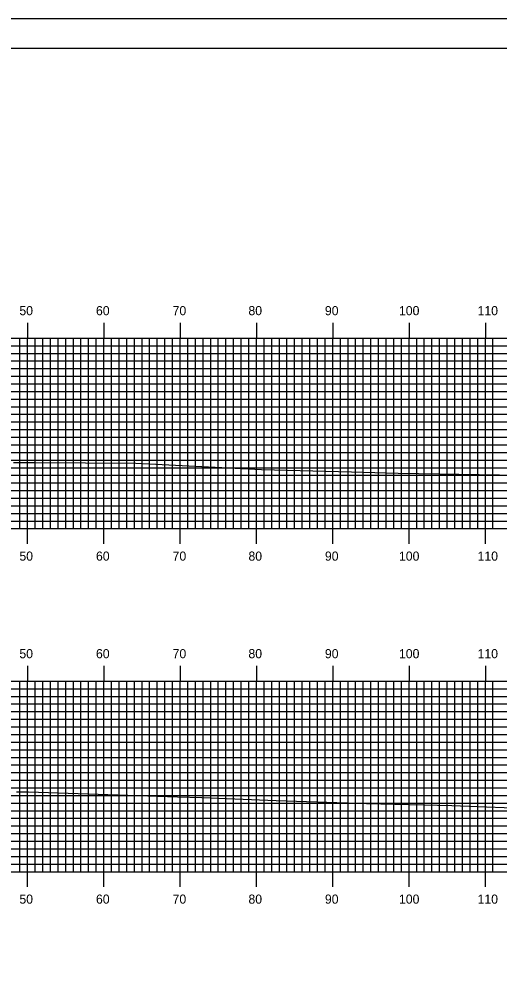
# Model space of a CAD drawing. Extents: x 1780680 to 1781023, y 442591 to 442811.
# Drawn here: x 1780894.2 to 1780957.2, y 442686.7 to 442810.5 of the extents above; entities that cross this region are included whole.
import ezdxf

# ---------------------------------------------------------------- set-up
doc = ezdxf.new("R2010")
doc.units = 0
for name, color, linetype in [('BORDER', 7, 'Continuous'), ('H_V ANNOTATION', 7, 'Continuous'), ('MAJOR', 7, 'Continuous'), ('MINOR', 7, 'Continuous'), ('PLOT BOUNDARY', 7, 'Continuous'), ('S_Roadway_Centerline', 7, 'Continuous')]:
    doc.layers.add(name, color=color, linetype=linetype)

msp = doc.modelspace()

# ---------------------------------------------------------------- linework, layer by layer
at = {"layer": 'BORDER'}
msp.add_lwpolyline([(1780695.78, 442596.67), (1781015.78, 442596.67), (1781015.78, 442806.67), (1780695.78, 442806.67)], close=True, dxfattribs=at)
at = {"layer": 'MAJOR'}
for p, q in [((1780895.38, 442770.67), (1780895.38, 442768.67)), ((1780905.38, 442770.67), (1780905.38, 442768.67)), ((1780915.38, 442770.67), (1780915.38, 442768.67)), ((1780925.38, 442770.67), (1780925.38, 442768.67)), ((1780935.38, 442770.67), (1780935.38, 442768.67)), ((1780945.38, 442770.67), (1780945.38, 442768.67)), ((1780955.38, 442770.67), (1780955.38, 442768.67)), ((1780705.38, 442768.67), (1780985.38, 442768.67)), ((1780705.38, 442768.67), (1780985.38, 442768.67)), ((1780895.38, 442743.67), (1780895.38, 442768.67)), ((1780905.38, 442743.67), (1780905.38, 442768.67)), ((1780915.38, 442743.67), (1780915.38, 442768.67)), ((1780925.38, 442743.67), (1780925.38, 442768.67)), ((1780935.38, 442743.67), (1780935.38, 442768.67)), ((1780945.38, 442743.67), (1780945.38, 442768.67)), ((1780955.38, 442743.67), (1780955.38, 442768.67)), ((1780705.38, 442763.67), (1780985.38, 442763.67)), ((1780705.38, 442758.67), (1780985.38, 442758.67)), ((1780705.38, 442753.67), (1780985.38, 442753.67)), ((1780705.38, 442748.67), (1780985.38, 442748.67)), ((1780705.38, 442743.67), (1780985.38, 442743.67)), ((1780705.38, 442743.67), (1780985.38, 442743.67)), ((1780895.38, 442741.66), (1780895.38, 442743.67)), ((1780905.38, 442741.66), (1780905.38, 442743.67)), ((1780915.38, 442741.66), (1780915.38, 442743.67)), ((1780925.38, 442741.66), (1780925.38, 442743.67)), ((1780935.38, 442741.66), (1780935.38, 442743.67)), ((1780945.38, 442741.66), (1780945.38, 442743.67)), ((1780955.38, 442741.66), (1780955.38, 442743.67)), ((1780895.38, 442725.67), (1780895.38, 442723.67)), ((1780905.38, 442725.67), (1780905.38, 442723.67)), ((1780915.38, 442725.67), (1780915.38, 442723.67)), ((1780925.38, 442725.67), (1780925.38, 442723.67)), ((1780935.38, 442725.67), (1780935.38, 442723.67)), ((1780945.38, 442725.67), (1780945.38, 442723.67)), ((1780955.38, 442725.67), (1780955.38, 442723.67)), ((1780705.38, 442723.67), (1780985.38, 442723.67)), ((1780705.38, 442723.67), (1780985.38, 442723.67)), ((1780895.38, 442698.67), (1780895.38, 442723.67)), ((1780905.38, 442698.67), (1780905.38, 442723.67)), ((1780915.38, 442698.67), (1780915.38, 442723.67)), ((1780925.38, 442698.67), (1780925.38, 442723.67)), ((1780935.38, 442698.67), (1780935.38, 442723.67)), ((1780945.38, 442698.67), (1780945.38, 442723.67)), ((1780955.38, 442698.67), (1780955.38, 442723.67)), ((1780705.38, 442718.67), (1780985.38, 442718.67)), ((1780705.38, 442713.67), (1780985.38, 442713.67)), ((1780705.38, 442708.67), (1780985.38, 442708.67)), ((1780705.38, 442703.67), (1780985.38, 442703.67)), ((1780705.38, 442698.67), (1780985.38, 442698.67)), ((1780705.38, 442698.67), (1780985.38, 442698.67)), ((1780895.38, 442696.66), (1780895.38, 442698.67)), ((1780905.38, 442696.66), (1780905.38, 442698.67)), ((1780915.38, 442696.66), (1780915.38, 442698.67)), ((1780925.38, 442696.66), (1780925.38, 442698.67)), ((1780935.38, 442696.66), (1780935.38, 442698.67)), ((1780945.38, 442696.66), (1780945.38, 442698.67)), ((1780955.38, 442696.66), (1780955.38, 442698.67))]:
    msp.add_line(p, q, dxfattribs=at)
at = {"layer": 'MINOR'}
for p, q in [((1780894.38, 442743.67), (1780894.38, 442768.67)), ((1780896.38, 442743.67), (1780896.38, 442768.67)), ((1780897.38, 442743.67), (1780897.38, 442768.67)), ((1780898.38, 442743.67), (1780898.38, 442768.67)), ((1780899.38, 442743.67), (1780899.38, 442768.67)), ((1780900.38, 442743.67), (1780900.38, 442768.67)), ((1780901.38, 442743.67), (1780901.38, 442768.67)), ((1780902.38, 442743.67), (1780902.38, 442768.67)), ((1780903.38, 442743.67), (1780903.38, 442768.67)), ((1780904.38, 442743.67), (1780904.38, 442768.67)), ((1780906.38, 442743.67), (1780906.38, 442768.67)), ((1780907.38, 442743.67), (1780907.38, 442768.67)), ((1780908.38, 442743.67), (1780908.38, 442768.67)), ((1780909.38, 442743.67), (1780909.38, 442768.67)), ((1780910.38, 442743.67), (1780910.38, 442768.67)), ((1780911.38, 442743.67), (1780911.38, 442768.67)), ((1780912.38, 442743.67), (1780912.38, 442768.67)), ((1780913.38, 442743.67), (1780913.38, 442768.67)), ((1780914.38, 442743.67), (1780914.38, 442768.67)), ((1780916.38, 442743.67), (1780916.38, 442768.67)), ((1780917.38, 442743.67), (1780917.38, 442768.67)), ((1780918.38, 442743.67), (1780918.38, 442768.67)), ((1780919.38, 442743.67), (1780919.38, 442768.67)), ((1780920.38, 442743.67), (1780920.38, 442768.67)), ((1780921.38, 442743.67), (1780921.38, 442768.67)), ((1780922.38, 442743.67), (1780922.38, 442768.67)), ((1780923.38, 442743.67), (1780923.38, 442768.67)), ((1780924.38, 442743.67), (1780924.38, 442768.67)), ((1780926.38, 442743.67), (1780926.38, 442768.67)), ((1780927.38, 442743.67), (1780927.38, 442768.67)), ((1780928.38, 442743.67), (1780928.38, 442768.67)), ((1780929.38, 442743.67), (1780929.38, 442768.67)), ((1780930.38, 442743.67), (1780930.38, 442768.67)), ((1780931.38, 442743.67), (1780931.38, 442768.67)), ((1780932.38, 442743.67), (1780932.38, 442768.67)), ((1780933.38, 442743.67), (1780933.38, 442768.67)), ((1780934.38, 442743.67), (1780934.38, 442768.67)), ((1780936.38, 442743.67), (1780936.38, 442768.67)), ((1780937.38, 442743.67), (1780937.38, 442768.67)), ((1780938.38, 442743.67), (1780938.38, 442768.67)), ((1780939.38, 442743.67), (1780939.38, 442768.67)), ((1780940.38, 442743.67), (1780940.38, 442768.67)), ((1780941.38, 442743.67), (1780941.38, 442768.67)), ((1780942.38, 442743.67), (1780942.38, 442768.67)), ((1780943.38, 442743.67), (1780943.38, 442768.67)), ((1780944.38, 442743.67), (1780944.38, 442768.67)), ((1780946.38, 442743.67), (1780946.38, 442768.67)), ((1780947.38, 442743.67), (1780947.38, 442768.67)), ((1780948.38, 442743.67), (1780948.38, 442768.67)), ((1780949.38, 442743.67), (1780949.38, 442768.67)), ((1780950.38, 442743.67), (1780950.38, 442768.67)), ((1780951.38, 442743.67), (1780951.38, 442768.67)), ((1780952.38, 442743.67), (1780952.38, 442768.67)), ((1780953.38, 442743.67), (1780953.38, 442768.67)), ((1780954.38, 442743.67), (1780954.38, 442768.67)), ((1780956.38, 442743.67), (1780956.38, 442768.67)), ((1780705.38, 442767.67), (1780985.38, 442767.67)), ((1780705.38, 442766.67), (1780985.38, 442766.67)), ((1780705.38, 442765.67), (1780985.38, 442765.67)), ((1780705.38, 442764.67), (1780985.38, 442764.67)), ((1780705.38, 442762.67), (1780985.38, 442762.67)), ((1780705.38, 442761.67), (1780985.38, 442761.67)), ((1780705.38, 442760.67), (1780985.38, 442760.67)), ((1780705.38, 442759.67), (1780985.38, 442759.67)), ((1780705.38, 442757.67), (1780985.38, 442757.67)), ((1780705.38, 442756.67), (1780985.38, 442756.67)), ((1780705.38, 442755.67), (1780985.38, 442755.67)), ((1780705.38, 442754.67), (1780985.38, 442754.67)), ((1780705.38, 442752.67), (1780985.38, 442752.67)), ((1780705.38, 442751.67), (1780985.38, 442751.67)), ((1780705.38, 442750.67), (1780985.38, 442750.67)), ((1780705.38, 442749.67), (1780985.38, 442749.67)), ((1780705.38, 442747.67), (1780985.38, 442747.67)), ((1780705.38, 442746.67), (1780985.38, 442746.67)), ((1780705.38, 442745.67), (1780985.38, 442745.67)), ((1780705.38, 442744.67), (1780985.38, 442744.67)), ((1780894.38, 442698.67), (1780894.38, 442723.67)), ((1780896.38, 442698.67), (1780896.38, 442723.67)), ((1780897.38, 442698.67), (1780897.38, 442723.67)), ((1780898.38, 442698.67), (1780898.38, 442723.67)), ((1780899.38, 442698.67), (1780899.38, 442723.67)), ((1780900.38, 442698.67), (1780900.38, 442723.67)), ((1780901.38, 442698.67), (1780901.38, 442723.67)), ((1780902.38, 442698.67), (1780902.38, 442723.67)), ((1780903.38, 442698.67), (1780903.38, 442723.67)), ((1780904.38, 442698.67), (1780904.38, 442723.67)), ((1780906.38, 442698.67), (1780906.38, 442723.67)), ((1780907.38, 442698.67), (1780907.38, 442723.67)), ((1780908.38, 442698.67), (1780908.38, 442723.67)), ((1780909.38, 442698.67), (1780909.38, 442723.67)), ((1780910.38, 442698.67), (1780910.38, 442723.67)), ((1780911.38, 442698.67), (1780911.38, 442723.67)), ((1780912.38, 442698.67), (1780912.38, 442723.67)), ((1780913.38, 442698.67), (1780913.38, 442723.67)), ((1780914.38, 442698.67), (1780914.38, 442723.67)), ((1780916.38, 442698.67), (1780916.38, 442723.67)), ((1780917.38, 442698.67), (1780917.38, 442723.67)), ((1780918.38, 442698.67), (1780918.38, 442723.67)), ((1780919.38, 442698.67), (1780919.38, 442723.67)), ((1780920.38, 442698.67), (1780920.38, 442723.67)), ((1780921.38, 442698.67), (1780921.38, 442723.67)), ((1780922.38, 442698.67), (1780922.38, 442723.67)), ((1780923.38, 442698.67), (1780923.38, 442723.67)), ((1780924.38, 442698.67), (1780924.38, 442723.67)), ((1780926.38, 442698.67), (1780926.38, 442723.67)), ((1780927.38, 442698.67), (1780927.38, 442723.67)), ((1780928.38, 442698.67), (1780928.38, 442723.67)), ((1780929.38, 442698.67), (1780929.38, 442723.67)), ((1780930.38, 442698.67), (1780930.38, 442723.67)), ((1780931.38, 442698.67), (1780931.38, 442723.67)), ((1780932.38, 442698.67), (1780932.38, 442723.67)), ((1780933.38, 442698.67), (1780933.38, 442723.67)), ((1780934.38, 442698.67), (1780934.38, 442723.67)), ((1780936.38, 442698.67), (1780936.38, 442723.67)), ((1780937.38, 442698.67), (1780937.38, 442723.67)), ((1780938.38, 442698.67), (1780938.38, 442723.67)), ((1780939.38, 442698.67), (1780939.38, 442723.67)), ((1780940.38, 442698.67), (1780940.38, 442723.67)), ((1780941.38, 442698.67), (1780941.38, 442723.67)), ((1780942.38, 442698.67), (1780942.38, 442723.67)), ((1780943.38, 442698.67), (1780943.38, 442723.67)), ((1780944.38, 442698.67), (1780944.38, 442723.67)), ((1780946.38, 442698.67), (1780946.38, 442723.67)), ((1780947.38, 442698.67), (1780947.38, 442723.67)), ((1780948.38, 442698.67), (1780948.38, 442723.67)), ((1780949.38, 442698.67), (1780949.38, 442723.67)), ((1780950.38, 442698.67), (1780950.38, 442723.67)), ((1780951.38, 442698.67), (1780951.38, 442723.67)), ((1780952.38, 442698.67), (1780952.38, 442723.67)), ((1780953.38, 442698.67), (1780953.38, 442723.67)), ((1780954.38, 442698.67), (1780954.38, 442723.67)), ((1780956.38, 442698.67), (1780956.38, 442723.67)), ((1780705.38, 442722.67), (1780985.38, 442722.67)), ((1780705.38, 442721.67), (1780985.38, 442721.67)), ((1780705.38, 442720.67), (1780985.38, 442720.67)), ((1780705.38, 442719.67), (1780985.38, 442719.67)), ((1780705.38, 442717.67), (1780985.38, 442717.67)), ((1780705.38, 442716.67), (1780985.38, 442716.67)), ((1780705.38, 442715.67), (1780985.38, 442715.67)), ((1780705.38, 442714.67), (1780985.38, 442714.67)), ((1780705.38, 442712.67), (1780985.38, 442712.67)), ((1780705.38, 442711.67), (1780985.38, 442711.67)), ((1780705.38, 442710.67), (1780985.38, 442710.67)), ((1780705.38, 442709.67), (1780985.38, 442709.67)), ((1780705.38, 442707.67), (1780985.38, 442707.67)), ((1780705.38, 442706.67), (1780985.38, 442706.67)), ((1780705.38, 442705.67), (1780985.38, 442705.67)), ((1780705.38, 442704.67), (1780985.38, 442704.67)), ((1780705.38, 442702.67), (1780985.38, 442702.67)), ((1780705.38, 442701.67), (1780985.38, 442701.67)), ((1780705.38, 442700.67), (1780985.38, 442700.67)), ((1780705.38, 442699.67), (1780985.38, 442699.67))]:
    msp.add_line(p, q, dxfattribs=at)
at = {"layer": 'PLOT BOUNDARY'}
msp.add_lwpolyline([(1780679.59, 442590.55), (1781019.59, 442590.55), (1781019.59, 442810.55), (1780679.59, 442810.55)], close=True, dxfattribs=at)
at = {"layer": 'S_Roadway_Centerline'}
for points in [[(1780893.56, 442752.35), (1780894.93, 442752.37), (1780896.39, 442752.34), (1780909.57, 442752.25), (1780926.04, 442751.41), (1780937.83, 442751.12), (1780943.94, 442750.97), (1780959.88, 442750.68), (1780968.72, 442750.1), (1780976.21, 442749.3), (1780984.09, 442749.4), (1780985.38, 442749.36)], [(1780893.94, 442709.16), (1780895.49, 442709.14), (1780915.02, 442708.5), (1780918.2, 442708.4), (1780927.97, 442707.99), (1780938.58, 442707.66), (1780939.79, 442707.63), (1780950.99, 442707.37), (1780962.4, 442706.9), (1780962.78, 442706.88), (1780974.48, 442706.35), (1780984.78, 442706.34), (1780985.38, 442706.32)]]:
    msp.add_lwpolyline(points, dxfattribs=at)

# ---------------------------------------------------------------- texts
at = {"layer": 'H_V ANNOTATION'}
for s, p in [('50', (1780894.31, 442771.67)), ('60', (1780904.35, 442771.67)), ('70', (1780914.39, 442771.67)), ('80', (1780924.33, 442771.67)), ('90', (1780934.35, 442771.67)), ('100', (1780944.06, 442771.67)), ('110', (1780954.36, 442771.67)), ('50', (1780894.31, 442739.47)), ('60', (1780904.35, 442739.47)), ('70', (1780914.39, 442739.47)), ('80', (1780924.33, 442739.47)), ('90', (1780934.35, 442739.47)), ('100', (1780944.06, 442739.47)), ('110', (1780954.36, 442739.47)), ('50', (1780894.31, 442726.67)), ('60', (1780904.35, 442726.67)), ('70', (1780914.39, 442726.67)), ('80', (1780924.33, 442726.67)), ('90', (1780934.35, 442726.67)), ('100', (1780944.06, 442726.67)), ('110', (1780954.36, 442726.67)), ('50', (1780894.31, 442694.47)), ('60', (1780904.35, 442694.47)), ('70', (1780914.39, 442694.47)), ('80', (1780924.33, 442694.47)), ('90', (1780934.35, 442694.47)), ('100', (1780944.06, 442694.47)), ('110', (1780954.36, 442694.47))]:
    msp.add_text(s, height=1.2, dxfattribs=at).set_placement(p)

doc.saveas('drawing.dxf')
